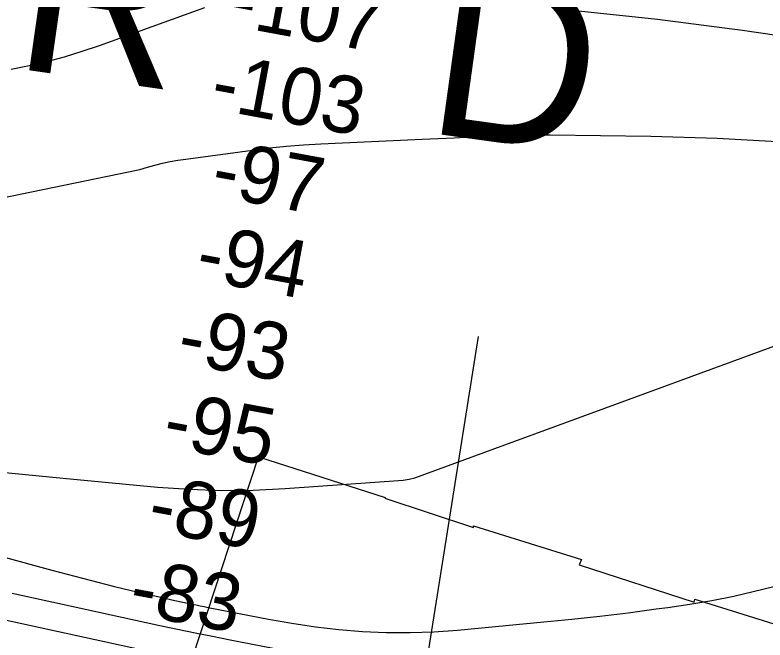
# Model space of a CAD drawing. Extents: x 3677843 to 3715951, y 511991 to 537744.
# Drawn here: x 3689113 to 3689993, y 531851 to 532584 of the extents above; entities that cross this region are included whole.
import ezdxf

# ---------------------------------------------------------------- set-up
doc = ezdxf.new("R2010")
doc.units = 0
for name, color, linetype in [('V-RIVR-IDEN', 7, 'Continuous'), ('V-RIVR-RANG', 7, 'Continuous'), ('V-RRAP-RVMT', 7, 'Continuous'), ('V-TOPO-MAJR', 7, 'Continuous'), ('V-TOPO-MINR', 7, 'Continuous')]:
    doc.layers.add(name, color=color, linetype=linetype)

msp = doc.modelspace()

# ---------------------------------------------------------------- linework, layer by layer
at = {"layer": 'V-RIVR-RANG'}
msp.add_line((3689518.8, 531337.98), (3689656.78, 532207.1), dxfattribs=at)
at = {"layer": 'V-RRAP-RVMT'}
for points in [[(3689278.47, 531699), (3689398.82, 532065.88)], [(3689398.82, 532065.88), (3689547.19, 532018.11), (3689546.85, 532017.3), (3689651.02, 531983.02), (3689651.05, 531984.96), (3689777.84, 531945.32), (3689775.1, 531939.17), (3689909.69, 531895.27), (3689910.48, 531898.58), (3690059.55, 531852.01), (3690057.16, 531844.99)]]:
    msp.add_lwpolyline(points, dxfattribs=at)
at = {"layer": 'V-TOPO-MAJR'}
msp.add_lwpolyline([(3688320.33, 532209.56), (3689259.71, 532403.13), (3689268.48, 532405.86), (3689277.34, 532408.3), (3689286.3, 532410.39), (3689295.3, 532412.28), (3689304.35, 532413.87), (3689313.45, 532415.27), (3689391.75, 532425.97), (3689411.71, 532428.42), (3689431.71, 532430.51), (3689451.76, 532432.06), (3689471.83, 532433.24), (3689590.9, 532438.65), (3689609.65, 532439.51), (3689628.41, 532440.39), (3689647.16, 532441.3), (3689665.92, 532442.22), (3689684.67, 532442.97), (3689703.43, 532443.5), (3689722.2, 532443.67), (3689740.97, 532443.61), (3689859, 532442.11), (3689936.7, 532439.8), (3690014.27, 532435.73)], dxfattribs=at)
at = {"layer": 'V-TOPO-MINR'}
for points in [[(3689108.47, 532520.75), (3689129.57, 532525.08), (3689150.52, 532530), (3689171.3, 532535.48), (3689191.85, 532541.81), (3689212.23, 532548.7), (3689335.68, 532593.29)], [(3689766.8, 532590.22), (3689866.71, 532579.44), (3689966.39, 532566.57), (3690065.89, 532552.33)], [(3689077.16, 532049.85), (3689169.76, 532040.65), (3689280.36, 532030.26), (3689317.73, 532027.68), (3689355.11, 532026.34), (3689392.52, 532026.86), (3689429.93, 532028.61), (3689568.37, 532038.56), (3689575.42, 532039.59), (3689582.26, 532041.27), (3690187.7, 532263.32), (3690216.7, 532264.64), (3690245.69, 532266.04), (3690274.68, 532267.64), (3690303.64, 532269.55), (3690332.59, 532271.66), (3690573.14, 532290.48), (3691729.15, 531983.38)], [(3688975.78, 531981.91), (3689156.47, 531932.81), (3689174.37, 531928.01), (3689192.3, 531923.28), (3689210.25, 531918.68), (3689228.23, 531914.15), (3689231.42, 531913.36), (3689247.83, 531909.36), (3689264.27, 531905.46), (3689280.74, 531901.71), (3689297.24, 531898.05), (3689320.78, 531892.94), (3689325.52, 531891.93), (3689330.27, 531890.94), (3689335.03, 531889.97), (3689339.79, 531889.03), (3689410.54, 531875.28), (3689437.98, 531870.48), (3689465.51, 531866.38), (3689493.17, 531863.32), (3689520.93, 531860.95), (3689548.74, 531859.78), (3689576.54, 531859.49), (3689604.32, 531860.54), (3689632.09, 531862.48), (3689733.4, 531871.98), (3689766.4, 531875.29), (3689799.36, 531878.89), (3689832.27, 531882.91), (3689865.15, 531887.22), (3689878.94, 531889.12), (3689904.84, 531893), (3689930.67, 531897.29), (3689956.4, 531902.18), (3690409.44, 532011.69)], [(3689109.66, 531905.79), (3689181.19, 531890.15), (3689283.22, 531868.02), (3689303.77, 531863.63), (3689324.35, 531859.33), (3689344.95, 531855.16), (3689365.57, 531851.08), (3689709, 531784.32)], [(3689065.17, 531882.27), (3689293.27, 531832.81)]]:
    msp.add_lwpolyline(points, dxfattribs=at)

# ---------------------------------------------------------------- texts
at = {"layer": 'V-RIVR-IDEN'}
for s, rotation, p in [('R', 351.88837, (3689108.15, 532522.63)), ('D', 352.11212, (3689591.89, 532447))]:
    msp.add_text(s, height=200, rotation=rotation, dxfattribs=at).set_placement(p)
at = {"layer": 'V-RIVR-RANG'}
for s, p in [('-107', (3689361.86, 532572.71)), ('-103', (3689340.31, 532475)), ('-97', (3689341.08, 532373.16)), ('-94', (3689322.9, 532274.83)), ('-93', (3689301.1, 532177.17)), ('-95', (3689284.23, 532078.59)), ('-89', (3689266.57, 531980.16)), ('-83', (3689244.77, 531882.5))]:
    msp.add_text(s, height=67, rotation=349.52056, dxfattribs=at).set_placement(p)

doc.saveas('drawing.dxf')
